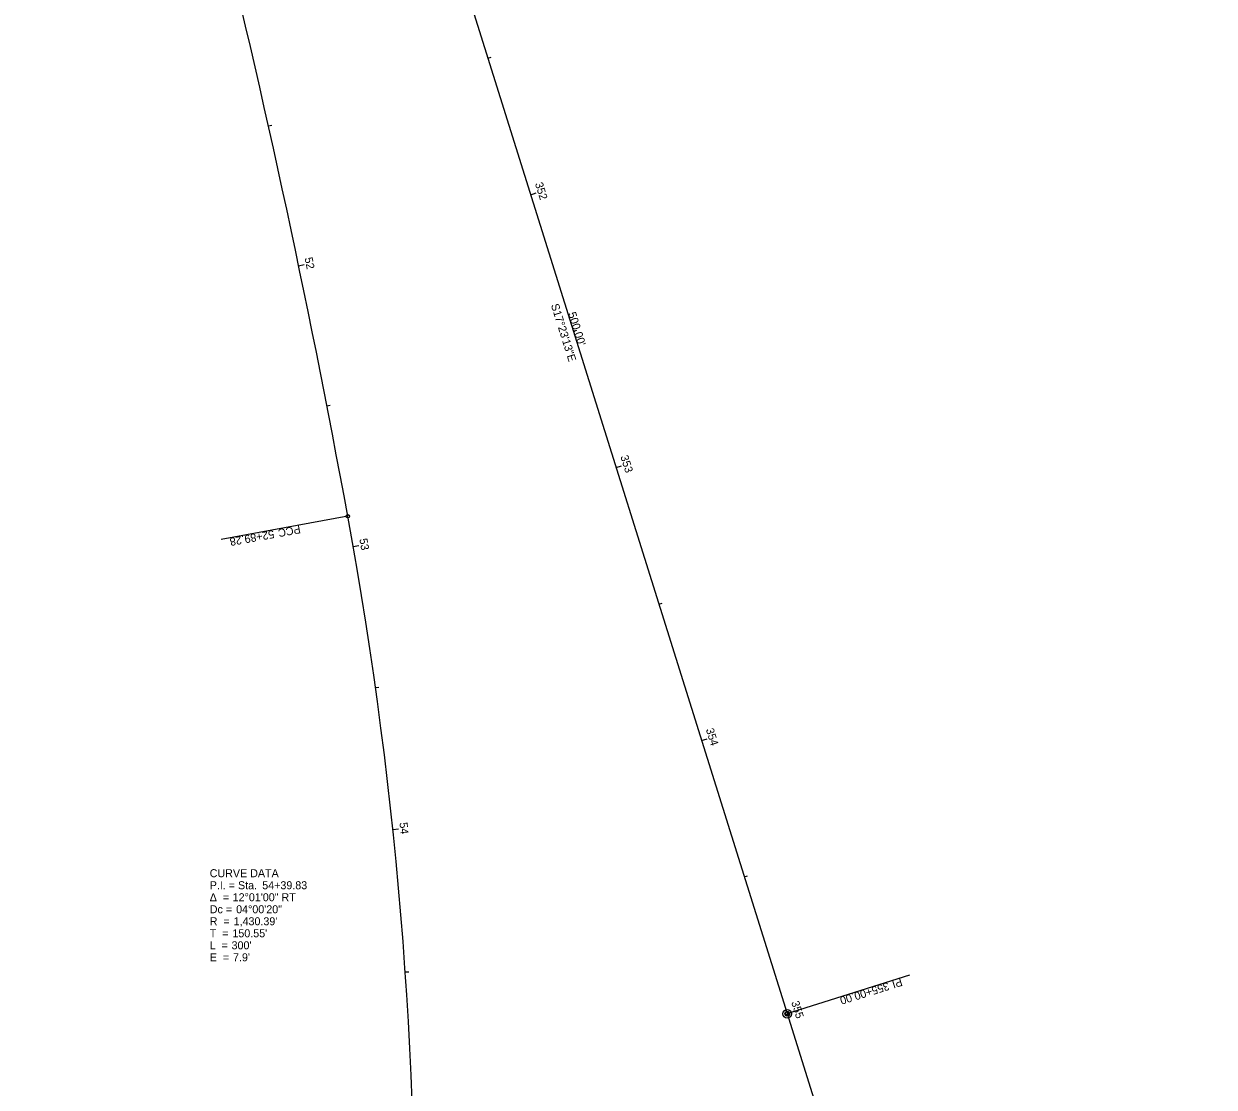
# Model space of a CAD drawing. Extents: x 1918148 to 1920349, y 624677 to 627727.
# Drawn here: x 1918749.8 to 1919166.2, y 626585.1 to 626957 of the extents above; entities that cross this region are included whole.
import ezdxf

# ---------------------------------------------------------------- set-up
doc = ezdxf.new("R2010")
doc.units = 0
for name, color, linetype in [('_CIVIL_CONSTRUCTION', 7, 'Continuous'), ('RS_Raster1', 7, 'Continuous'), ('RW_X_CL', 7, 'Continuous'), ('RW_X_CL_100_Bearings', 7, 'Continuous'), ('RW_X_CL_100_Cardinal_Points', 7, 'Continuous'), ('RW_X_CL_100_Curve_Data', 7, 'Continuous'), ('SV_X_Mon_Cells_Found', 7, 'Continuous')]:
    doc.layers.add(name, color=color, linetype=linetype)

msp = doc.modelspace()

# ---------------------------------------------------------------- linework, layer by layer
at = {"layer": 'RS_Raster1'}
for p, q in [((1918867.35, 627088.08), (1919016.77, 626610.92)), ((1919016.77, 626610.92), (1919166.18, 626133.77))]:
    msp.add_line(p, q, dxfattribs=at)
for centre, radius, start, end in [((1915258.46, 626122.9), 3664.95, 10.40444, 17.70444), ((1917456.28, 626526.45), 1430.39, 358.38778, 10.40444)]:
    msp.add_arc(centre, radius, start, end, dxfattribs=at)
at = {"layer": 'RW_X_CL'}
for p, q in [((1918863.15, 626784.77), (1918818.89, 626776.65)), ((1919016.77, 626610.92), (1919059.71, 626624.37))]:
    msp.add_line(p, q, dxfattribs=at)
for centre in [(1918863.15, 626784.77), (1919016.77, 626610.92)]:
    msp.add_circle(centre, 0.6, dxfattribs=at)
at = {"layer": 'RW_X_CL_100_Cardinal_Points'}
for p, q in [((1918912.18, 626944.93), (1918913.32, 626945.29)), ((1918835.4, 626921.25), (1918836.57, 626921.51)), ((1918927.12, 626897.21), (1918929.03, 626897.81)), ((1918845.96, 626872.38), (1918847.92, 626872.79)), ((1918942.06, 626849.5), (1918943.21, 626849.86)), ((1918855.85, 626823.37), (1918857.03, 626823.59)), ((1918957, 626801.78), (1918958.91, 626802.38)), ((1918865.05, 626774.22), (1918867.02, 626774.57)), ((1918971.94, 626754.07), (1918973.09, 626754.43)), ((1918872.85, 626724.83), (1918874.03, 626725)), ((1918986.88, 626706.35), (1918988.79, 626706.95)), ((1918878.91, 626675.21), (1918880.9, 626675.41)), ((1919001.83, 626658.64), (1919002.97, 626659)), ((1918883.24, 626625.4), (1918884.44, 626625.48)), ((1919016.77, 626610.92), (1919018.68, 626611.52))]:
    msp.add_line(p, q, dxfattribs=at)
at = {"layer": 'SV_X_Mon_Cells_Found'}
for radius in [1.5, 0.8]:
    msp.add_circle((1919016.85, 626610.8), radius, dxfattribs=at)

# ---------------------------------------------------------------- texts
at = {"layer": '_CIVIL_CONSTRUCTION'}
msp.add_text('S17°23\'13"E', height=2.8, rotation=287.387, dxfattribs=at).set_placement((1918934.17, 626858.63))
at = {"layer": 'RW_X_CL'}
for s, rotation, p in [('52+89.28', 190.4044, (1918837.14, 626779.95)), ('PCC', 190.4044, (1918846.34, 626781.64)), ('355+00.00', 197.387, (1919052.02, 626621.91)), ('PI', 197.387, (1919056.58, 626623.34))]:
    msp.add_text(s, height=2.8, rotation=rotation, dxfattribs=at).set_placement(p)
at = {"layer": 'RW_X_CL_100_Bearings'}
for s, p in [('CURVE DATA', (1918814.86, 626658.54)), ('P.I. = Sta. ', (1918814.86, 626654.34)), ('54+39.83', (1918833.23, 626654.34)), ('Δ  = ', (1918814.86, 626650.14)), ('12°01\'00" RT', (1918822.88, 626650.14)), ('Dc = ', (1918814.86, 626645.94)), ('04°00\'20"', (1918824.1, 626645.94)), ('R  = ', (1918814.86, 626641.74)), ("1,430.39'", (1918823.22, 626641.74)), ('T  = ', (1918814.86, 626637.54)), ("150.55'", (1918822.79, 626637.54)), ("300'", (1918822.5, 626633.34)), ('L  = ', (1918814.86, 626633.34)), ('E  = ', (1918814.86, 626629.14)), ("7.9'", (1918823.01, 626629.14))]:
    msp.add_text(s, height=2.8, dxfattribs=at).set_placement(p)
at = {"layer": 'RW_X_CL_100_Cardinal_Points'}
for s, rotation, p in [('352', 287.387, (1918928.57, 626901.1)), ('52', 281.8002, (1918848.01, 626875.04)), ('353', 287.387, (1918958.46, 626805.66)), ('53', 279.9749, (1918867.18, 626776.8)), ('354', 287.387, (1918988.35, 626710.2)), ('54', 275.9693, (1918881.22, 626677.61)), ('355', 287.387, (1919018.21, 626614.83))]:
    msp.add_text(s, height=2.8, rotation=rotation, dxfattribs=at).set_placement(p)
at = {"layer": 'RW_X_CL_100_Curve_Data'}
msp.add_text("500.00'", height=2.8, rotation=287.387, dxfattribs=at).set_placement((1918940.17, 626855.7))

doc.saveas('drawing.dxf')
